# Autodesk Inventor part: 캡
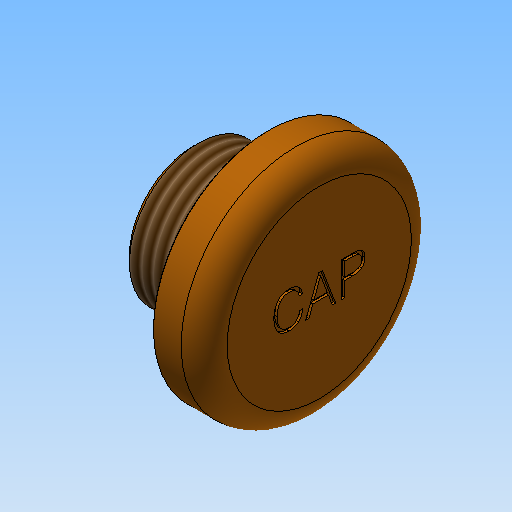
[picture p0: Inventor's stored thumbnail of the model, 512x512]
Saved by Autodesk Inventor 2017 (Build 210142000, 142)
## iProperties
Created: 2017-06
Part Number: 캡
Material: ABS 플라스틱
Document SubType Name: Modeling
Designer: mduedu
Density: 1 g/cm^3
Appearance: 주황색
Author: mduedu
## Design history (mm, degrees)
sketch "스케치1"
  geometry: L1 (0, 0)-(11, 0); L2 (11, 0)-(11, 10); L3 (11, 10)-(6.5, 10); L4 (0, 6)-(0, 0); L5 (0, 6)-(6, 6); L6 (6, 6)-(6, 9); L7 (6, 9)-(6.5, 9); L8 (6.5, 9)-(6.5, 10)
  constraints: 16 end point, 2 horizontal, 2 parallel, 2 perpendicular, 2 point on line, 1 vertical
  dimensions: "d0" = 20 diameter of L3 L1; "d2" = 12 diameter of L5 L1; "d6" = 5 distance between parallel lines of L2 L6; "d7" = 0.5 distance between parallel lines of L8 L6; "d8" = 18 diameter of L7 L1; "d9" = 6 distance between parallel lines of L6 L4
revolve "회전1" sketch "스케치1" stored, may be unused: angle "d10" = 90 deg
hole "구멍1" diameter "d22" = 8; stored, may be unused: countersink angle "d26" = 90 deg, drill point angle "d28" = 0 deg; dims "d23" = 6, "d24" = 4, "d25" = 2, "d27" = 5, "d32" = 10, "d33" = 10
chamfer "모따기1" distance "d13" = 0.5; stored, may be unused: second distance "d14" = 2, angle "d15" = 45 deg
fillet "모깎기3" dims "d29" = 1
fillet "모깎기1" dims "d16" = 0.1
fillet "모깎기2" dims "d17" = 2
sketch "스케치3"
  geometry: 2 further points
  constraints: 1 coincident, 1 other
feature "엠보싱1" sketch "스케치3" dims "d16" = 0.1, "d18" = 0.2, "d19" = 0
feature "스레드1" dims "d30" = 10, "d31" = 0
node "솔리드1"
